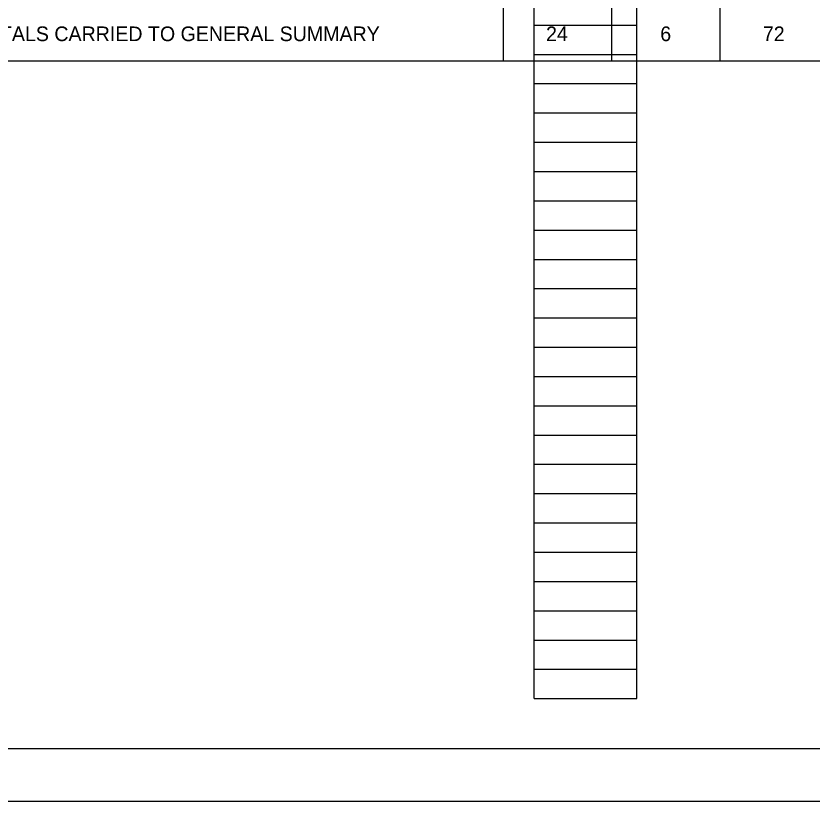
# Model space of a CAD drawing. Extents: x -6.8 to 34, y 0 to 22.
# Drawn here: x 18.73 to 26.34, y 0 to 7.51 of the extents above; entities that cross this region are included whole.
import ezdxf

# ---------------------------------------------------------------- set-up
doc = ezdxf.new("R2010")
doc.units = 0
for name, color, linetype in [('SH_Border', 7, 'Continuous'), ('SH_Cut_Line', 7, 'Continuous'), ('SH_Data', 7, 'Continuous'), ('SH_Text', 7, 'Continuous')]:
    doc.layers.add(name, color=color, linetype=linetype)

msp = doc.modelspace()

# ---------------------------------------------------------------- linework, layer by layer
at = {"layer": 'SH_Border'}
msp.add_lwpolyline([(1.5, 21.5), (33.5, 21.5), (33.5, 0.5), (1.5, 0.5)], close=True, dxfattribs=at)
at = {"layer": 'SH_Cut_Line'}
msp.add_lwpolyline([(0, 0), (34, 0), (34, 22), (0, 22)], close=True, dxfattribs=at)
at = {"layer": 'SH_Data'}
for p, q in [((23.68, 0.98), (23.68, 21.14)), ((24.66, 0.98), (24.66, 21.14)), ((23.68, 7.42), (24.66, 7.42)), ((23.68, 7.14), (24.66, 7.14)), ((23.68, 6.86), (24.66, 6.86)), ((23.68, 6.58), (24.66, 6.58)), ((23.68, 6.3), (24.66, 6.3)), ((23.68, 6.02), (24.66, 6.02)), ((23.68, 5.74), (24.66, 5.74)), ((23.68, 5.46), (24.66, 5.46)), ((23.68, 5.18), (24.66, 5.18)), ((23.68, 4.9), (24.66, 4.9)), ((23.68, 4.62), (24.66, 4.62)), ((23.68, 4.34), (24.66, 4.34)), ((23.68, 4.06), (24.66, 4.06)), ((23.68, 3.78), (24.66, 3.78)), ((23.68, 3.5), (24.66, 3.5)), ((23.68, 3.22), (24.66, 3.22)), ((23.68, 2.94), (24.66, 2.94)), ((23.68, 2.66), (24.66, 2.66)), ((23.68, 2.38), (24.66, 2.38)), ((23.68, 2.1), (24.66, 2.1)), ((23.68, 1.82), (24.66, 1.82)), ((23.68, 1.54), (24.66, 1.54)), ((23.68, 1.26), (24.66, 1.26)), ((23.68, 0.98), (24.66, 0.98))]:
    msp.add_line(p, q, dxfattribs=at)
at = {"layer": 'SH_Text'}
for p, q in [((23.3842, 20.7884), (23.3842, 7.0776)), ((24.419, 20.7884), (24.419, 7.0776)), ((25.4537, 20.7884), (25.4537, 7.0776)), ((16.932, 7.0776), (31.6624, 7.0776))]:
    msp.add_line(p, q, dxfattribs=at)

# ---------------------------------------------------------------- texts
for s, p in [('TOTALS CARRIED TO GENERAL SUMMARY', (18.3136, 7.2663)), ('24', (23.793, 7.2663)), ('6', (24.8848, 7.2663)), ('72', (25.8655, 7.2663))]:
    msp.add_text(s, height=0.14, dxfattribs=at).set_placement(p)

doc.saveas('drawing.dxf')
